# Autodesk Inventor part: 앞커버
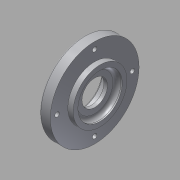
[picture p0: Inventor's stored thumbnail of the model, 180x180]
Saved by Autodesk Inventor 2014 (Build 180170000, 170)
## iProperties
Created: 2015-09
Part Number: 앞커버
Material: 알루미늄 6061
Document SubType Name: Modeling
Designer: mduedu
Density: 1 g/cm^3
Appearance: 알루미늄 - 평지
Author: mduedu
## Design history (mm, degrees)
sketch "스케치1"
  geometry: L1 (-8, 67)-(-12, 67); L2 (-12, 67)-(-12, 80); L3 (-12, 80)-(-20, 80); L4 (-20, 80)-(-20, 70.5); L5 (-23, 70.5)-(-23, 56.5); L6 (-23, 56.5)-(-8, 56.5); L7 (-8, 56.5)-(-8, 67); L8 (-79.5, 39.5)-(-79.5, 54.5) reference; L9 (48.5, 54.5)-(48.5, 39.5) reference; L10 (-79.5, 47)-(48.5, 47); L11 (-20, 70.5)-(-23, 70.5); 3 further points
  constraints: 18 end point, 6 parallel, 4 midpoint, 1 horizontal, 1 perpendicular, 1 vertical alignment
  dimensions: "d0" = 15 distance between parallel lines of L7 L5; "d2" = 19 diameter of L6 L10; "d3" = 40 diameter of L1 L10; "d5" = 4 distance of L1.start L1.end; "d6" = 66 diameter of L3 L10; "d7" = 8 distance of L2.end L3.end; "d8" = 47 diameter of L4.end L10
revolve "회전1" sketch "스케치1" stored, may be unused: angle "d4" = 90 deg
sketch "스케치2"
  geometry: C1 r 33 at (0, 0) reference; 2 further points
  constraints: 1 coincident
hole "구멍1" sketch "스케치2" at (0, 0) diameter "d11" = 33; stored, may be unused: countersink angle "d15" = 90 deg, drill point angle "d17" = 0 deg; dims "d12" = 6, "d13" = 4, "d14" = 2, "d16" = 4
fillet "모깎기1" dims "d18" = 3
fillet "모깎기2" dims "d19" = 1
sketch "스케치3"
  geometry: C1 r 33 at (0, 0) reference; 2 further points
  constraints: 1 coincident
hole "구멍2" sketch "스케치3" at (0, 0) diameter "d20" = 32; stored, may be unused: countersink angle "d24" = 90 deg, drill point angle "d26" = 0 deg; dims "d21" = 6, "d22" = 4, "d23" = 2, "d25" = 8.3
fillet "모깎기3" dims "d27" = 0.3
chamfer "모따기1" distance "d28" = 0.8; stored, may be unused: second distance "d29" = 2, angle "d30" = 30 deg
sketch "스케치4" dims "d31" = 56
  geometry: C1 r 33 at (0, 0) reference; 6 further points
  constraints: 2 vertical alignment, 1 coincident, 7 other
  dimensions: "d36" = 360 deg dimension on C1.centre point (0, 28) (derived)
sketch "스케치7"
  geometry: 4 further points
hole "구멍4" sketch "스케치7" at (0, 28), (-28, 0), (28, 0), (0, -28) diameter "d48" = 3.4; stored, may be unused: countersink angle "d52" = 90 deg, drill point angle "d54" = 0 deg; dims "d49" = 6, "d50" = 6.5, "d51" = 3.4, "d53" = 8
node "솔리드1"
node "참조1"
node "참조2"
